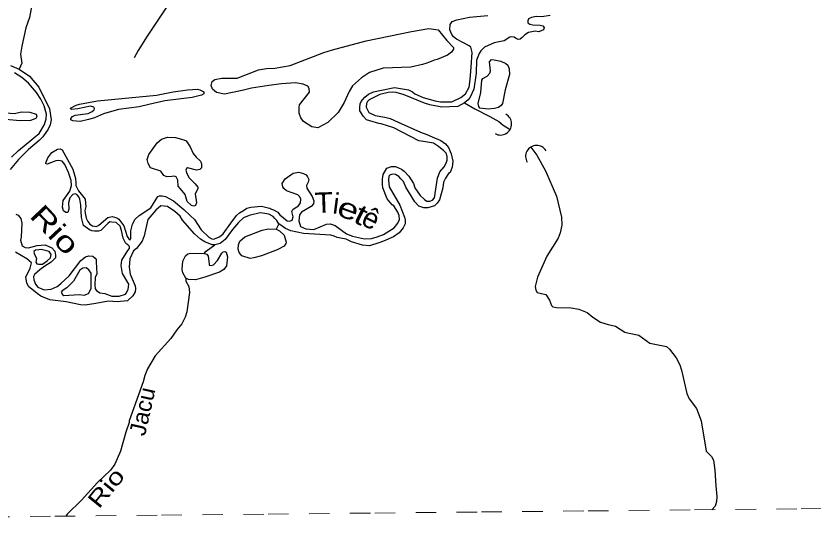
# Model space of a CAD drawing. Extents: x 346.5 to 372.4, y 7400.3 to 7428.2.
# Drawn here: x 350.815 to 354.71, y 7400.32 to 7402.808 of the extents above; entities that cross this region are included whole.
import ezdxf
from ezdxf.enums import TextEntityAlignment as Align

# ---------------------------------------------------------------- set-up
doc = ezdxf.new("R2010")
doc.units = 0
doc.header["$LTSCALE"] = 0.032
doc.linetypes.add('SHORT_DASHED', pattern=[2.7, 1.5, -1.2])
for name, color, linetype, lineweight in [('1', 7, 'Continuous', 25), ('11', 7, 'Continuous', 25), ('2', 7, 'Continuous', 25), ('53', 7, 'SHORT_DASHED', 13), ('7', 7, 'Continuous', 25)]:
    doc.layers.add(name, color=color, linetype=linetype, lineweight=lineweight)
doc.layers.add('61', color=7, linetype='Continuous')

msp = doc.modelspace()

# ---------------------------------------------------------------- linework, layer by layer
at = {"layer": '1'}
msp.add_lwpolyline([(352.0375, 7403.6183), (351.8749, 7403.388), (351.6956, 7403.1266), (351.6877, 7403.1138), (351.6908, 7403.0716), (351.6853, 7403.0612), (351.545, 7402.8413), (351.4565, 7402.709), (351.4119, 7402.6388), (351.3936, 7402.603)], dxfattribs=at)
at = {"layer": '11'}
for centre, start, end in [((353.1832, 7402.2798), 240.5966, 61.2995), ((353.3596, 7402.1208), 30.8412, 211.5442)]:
    msp.add_arc(centre, 0.0541, start, end, dxfattribs=at)
at = {"layer": '2'}
for points in [[(352.4969, 7402.3778), (352.5027, 7402.3902), (352.509, 7402.3985), (352.5203, 7402.4105), (352.5388, 7402.4249), (352.5631, 7402.437), (352.6013, 7402.4457), (352.6645, 7402.4574), (352.7337, 7402.4458), (352.7524, 7402.4372), (352.7642, 7402.4274), (352.8057, 7402.4094), (352.8638, 7402.3921), (352.8899, 7402.3872), (352.9449, 7402.3881), (352.9899, 7402.4084), (353.0116, 7402.4275), (353.0305, 7402.4602), (353.034, 7402.4963), (353.0398, 7402.5575), (353.0451, 7402.6289), (353.0384, 7402.6547), (353.0296, 7402.6618), (352.9683, 7402.6935), (352.9535, 7402.7052), (352.9449, 7402.7174), (352.9361, 7402.7391), (352.9364, 7402.7658), (352.9473, 7402.7801), (352.9702, 7402.7885), (353.0322, 7402.8013), (353.1214, 7402.8102)], [(353.4253, 7402.8091), (353.3842, 7402.8037), (353.3568, 7402.8049), (353.3347, 7402.8006), (353.3197, 7402.7932), (353.3158, 7402.784), (353.3169, 7402.7734), (353.3258, 7402.7679), (353.3418, 7402.7636), (353.3761, 7402.7624), (353.3899, 7402.7589), (353.3963, 7402.751), (353.3928, 7402.7402), (353.3709, 7402.7308), (353.3521, 7402.7325), (353.3202, 7402.7266), (353.3017, 7402.7152), (353.2886, 7402.702), (353.2796, 7402.6946), (353.2691, 7402.6931), (353.2559, 7402.6983), (353.2496, 7402.7041), (353.237, 7402.7062), (353.2284, 7402.7041), (353.2009, 7402.6862), (353.1519, 7402.6759), (353.1048, 7402.6551), (353.0877, 7402.6373), (353.0784, 7402.6249), (353.0658, 7402.5909), (353.0636, 7402.5276), (353.052, 7402.4502), (353.0353, 7402.4101), (353.0249, 7402.397), (353.0074, 7402.3835), (352.974, 7402.3659), (352.8966, 7402.3615), (352.8378, 7402.3732), (352.8124, 7402.3815), (352.7124, 7402.4217), (352.6724, 7402.4334), (352.6535, 7402.435), (352.6335, 7402.4337), (352.5929, 7402.4244), (352.542, 7402.3984), (352.5328, 7402.3897), (352.5278, 7402.3794), (352.5268, 7402.362), (352.5398, 7402.3354), (352.5705, 7402.3206), (352.6179, 7402.3131), (352.6446, 7402.3065), (352.6823, 7402.2879), (352.7919, 7402.2402), (352.8226, 7402.2283), (352.8499, 7402.2162), (352.8914, 7402.1983), (352.9145, 7402.1835), (352.9284, 7402.1645), (352.9412, 7402.1339), (352.9494, 7402.0977), (352.9472, 7402.068), (352.9377, 7402.0434), (352.9295, 7402.0371), (352.9145, 7402.0157), (352.9042, 7401.9951), (352.9005, 7401.9681), (352.8848, 7401.9091), (352.8742, 7401.8926), (352.8605, 7401.8793), (352.828, 7401.8698)], [(350.7883, 7402.5657), (350.8318, 7402.5473), (350.8816, 7402.5133), (350.9265, 7402.4595), (350.9796, 7402.3545), (350.9873, 7402.3008), (350.9828, 7402.2762), (350.9732, 7402.2545), (350.9468, 7402.2169), (350.9295, 7402.1986), (350.8763, 7402.1548), (350.8278, 7402.107), (350.7879, 7402.0566)], [(350.794, 7402.1169), (350.8276, 7402.1506), (350.8923, 7402.2035), (350.9044, 7402.2137), (350.9281, 7402.2328), (350.9544, 7402.2766), (350.9634, 7402.3047), (350.9642, 7402.3277), (350.9539, 7402.3686), (350.9377, 7402.4012), (350.9163, 7402.4337), (350.8771, 7402.4789), (350.8434, 7402.5074), (350.8076, 7402.5293)], [(351.9634, 7401.873), (352.0152, 7401.8777), (352.0539, 7401.869), (352.0637, 7401.8642), (352.0743, 7401.86), (352.0944, 7401.8488), (352.0986, 7401.8434), (352.1055, 7401.8366), (352.1413, 7401.807), (352.1539, 7401.8044), (352.1648, 7401.8098), (352.1701, 7401.826), (352.1659, 7401.8396), (352.1639, 7401.8525), (352.1683, 7401.8621), (352.1792, 7401.8707), (352.1961, 7401.8798), (352.2061, 7401.8948), (352.2077, 7401.9116), (352.2025, 7401.923), (352.1923, 7401.934), (352.1368, 7401.9523), (352.1238, 7401.9645), (352.1197, 7401.973), (352.1154, 7401.9884), (352.1303, 7402.0112), (352.1698, 7402.039), (352.1983, 7402.044), (352.2204, 7402.0383), (352.2333, 7402.0316), (352.2395, 7402.0219), (352.2462, 7402.0091), (352.2432, 7401.9958), (352.2349, 7401.9792), (352.2364, 7401.9669), (352.2632, 7401.9247), (352.2712, 7401.9035), (352.2691, 7401.8902), (352.2581, 7401.8766), (352.2106, 7401.8486), (352.2011, 7401.8365), (352.1983, 7401.8065), (352.2061, 7401.7796), (352.2316, 7401.7669), (352.2705, 7401.7645), (352.3331, 7401.7895), (352.3507, 7401.7914), (352.3744, 7401.7831), (352.4308, 7401.7428), (352.4597, 7401.7311), (352.5188, 7401.7191), (352.5529, 7401.7208), (352.5811, 7401.7284), (352.6121, 7401.7394), (352.6639, 7401.7721), (352.6817, 7401.7951), (352.6897, 7401.8129), (352.6881, 7401.8325), (352.6818, 7401.8488), (352.6623, 7401.8793), (352.6544, 7401.8842), (352.6297, 7401.9138), (352.6079, 7401.9677), (352.6064, 7401.9835), (352.6061, 7402.0099), (352.6097, 7402.033), (352.6281, 7402.0637), (352.6506, 7402.0721), (352.6698, 7402.0712), (352.6991, 7402.0588), (352.712, 7402.0494), (352.735, 7402.0255), (352.7572, 7401.9892), (352.7646, 7401.968), (352.7901, 7401.9299), (352.8116, 7401.9103), (352.8226, 7401.9031), (352.8373, 7401.9021), (352.85, 7401.9068), (352.8605, 7401.9182), (352.8747, 7402.0158), (352.8868, 7402.0459), (352.908, 7402.0708), (352.9151, 7402.0846), (352.9217, 7402.1023), (352.9226, 7402.1215), (352.9183, 7402.1364), (352.9059, 7402.1491), (352.8805, 7402.1705), (352.8562, 7402.1854), (352.8063, 7402.1934), (352.7847, 7402.1974), (352.6615, 7402.2607), (352.6003, 7402.2807), (352.5882, 7402.2815), (352.5442, 7402.2948), (352.529, 7402.3005), (352.5128, 7402.3168), (352.4956, 7402.3436), (352.4964, 7402.36), (352.4969, 7402.3778)], [(351.3288, 7401.5886), (351.333, 7401.6147), (351.3624, 7401.661), (351.3698, 7401.6714), (351.3698, 7401.6818), (351.3624, 7401.6885), (351.3527, 7401.6951), (351.3392, 7401.7213), (351.3312, 7401.7589), (351.3238, 7401.7797), (351.3054, 7401.7977), (351.2846, 7401.8008), (351.2742, 7401.8012), (351.2638, 7401.7931), (351.2305, 7401.7592), (351.2188, 7401.7554), (351.1999, 7401.7566), (351.1856, 7401.758), (351.1741, 7401.7631), (351.1457, 7401.7845), (351.1349, 7401.8221), (351.1322, 7401.8836), (351.1268, 7401.9127), (351.1227, 7401.9237), (351.1129, 7401.9354), (351.1048, 7401.9382), (351.0927, 7401.9359), (351.0784, 7401.9183), (351.0727, 7401.8941), (351.0733, 7401.8635), (351.0696, 7401.8478), (351.0595, 7401.8472), (351.0483, 7401.855), (351.0422, 7401.8741), (351.0458, 7401.9055), (351.0787, 7401.9509), (351.0863, 7401.9791), (351.0849, 7402.0028), (351.0717, 7402.0424), (351.0538, 7402.0822), (351.0404, 7402.0975), (351.0249, 7402.1012), (351.0097, 7402.0998), (350.9681, 7402.0842), (350.9621, 7402.0852), (350.9616, 7402.0895), (350.9713, 7402.1148), (350.9903, 7402.1408), (351.0185, 7402.1574), (351.0322, 7402.1584), (351.0406, 7402.1536), (351.0933, 7402.0583), (351.1057, 7402.014), (351.1074, 7401.9943), (351.1079, 7401.9792), (351.1206, 7401.9537), (351.1531, 7401.9123), (351.1556, 7401.8912), (351.1565, 7401.8758), (351.1526, 7401.8563), (351.1541, 7401.8445), (351.1578, 7401.82), (351.1659, 7401.8035), (351.1763, 7401.7901), (351.1889, 7401.7814), (351.2082, 7401.7792), (351.2208, 7401.7859), (351.2639, 7401.8225), (351.285, 7401.8269), (351.3082, 7401.8214), (351.3175, 7401.8144), (351.3427, 7401.7823), (351.3591, 7401.7301), (351.3664, 7401.718), (351.3731, 7401.7141), (351.3775, 7401.7208), (351.3764, 7401.7583), (351.3841, 7401.7897), (351.3986, 7401.8141), (351.418, 7401.8331), (351.4742, 7401.8696), (351.5092, 7401.9253), (351.5162, 7401.9291), (351.5296, 7401.9294), (351.5469, 7401.9255), (351.5846, 7401.9037), (351.6358, 7401.8626), (351.6674, 7401.8325), (351.6871, 7401.8128), (351.7208, 7401.7625), (351.7583, 7401.7266), (351.7731, 7401.718), (351.781, 7401.7168), (351.8098, 7401.7276), (351.8279, 7401.7429), (351.8646, 7401.7945), (351.8925, 7401.8323), (351.9083, 7401.8458), (351.9265, 7401.8567), (351.9429, 7401.8686), (351.9634, 7401.873)], [(352.828, 7401.8698), (352.8088, 7401.8707), (352.7844, 7401.8774), (352.7648, 7401.9001), (352.72, 7401.9707), (352.7095, 7401.998), (352.6962, 7402.0124), (352.6856, 7402.0237), (352.6698, 7402.0321), (352.6544, 7402.0347), (352.643, 7402.0301), (352.6372, 7402.024), (352.635, 7402.0069), (352.6394, 7401.9727), (352.6905, 7401.8834), (352.7138, 7401.8243), (352.7174, 7401.8102), (352.7167, 7401.792), (352.7081, 7401.7723), (352.6872, 7401.7472), (352.6594, 7401.7291), (352.6105, 7401.7066), (352.5885, 7401.6994), (352.5437, 7401.6848), (352.5087, 7401.6876), (352.4552, 7401.7045), (352.4295, 7401.7165), (352.3852, 7401.7254), (352.371, 7401.7308), (352.3543, 7401.7367), (352.2201, 7401.7453), (352.159, 7401.7569), (352.1329, 7401.7684), (352.0992, 7401.7912), (352.0896, 7401.8088), (352.0804, 7401.8176), (352.0719, 7401.8278), (352.0504, 7401.8397), (352.0311, 7401.843), (352.0094, 7401.846), (351.9552, 7401.8327), (351.9269, 7401.8207), (351.9021, 7401.7986), (351.8728, 7401.7643), (351.8383, 7401.7145), (351.813, 7401.6958), (351.7876, 7401.6889), (351.7738, 7401.6896), (351.7379, 7401.704), (351.7173, 7401.7166), (351.688, 7401.7437), (351.6292, 7401.8101), (351.6184, 7401.8286), (351.5923, 7401.8513), (351.5551, 7401.8764), (351.5238, 7401.8791), (351.4993, 7401.8586), (351.4595, 7401.8125), (351.4413, 7401.7324), (351.4323, 7401.7074), (351.4038, 7401.6712), (351.3904, 7401.66), (351.3722, 7401.6207), (351.3684, 7401.5803), (351.3738, 7401.5456), (351.3979, 7401.489), (351.3999, 7401.4747), (351.398, 7401.4594), (351.3862, 7401.4395), (351.3609, 7401.4161), (351.3097, 7401.4107), (351.2684, 7401.4135), (351.2049, 7401.4024), (351.1532, 7401.3951), (351.1307, 7401.3968), (351.0603, 7401.4106), (350.9812, 7401.4212), (350.9369, 7401.4384), (350.9186, 7401.4514), (350.8772, 7401.4864), (350.8684, 7401.504), (350.8644, 7401.5311), (350.8842, 7401.5745), (350.8911, 7401.6005), (350.8681, 7401.621), (350.8135, 7401.6539)], [(350.8153, 7401.8392), (350.8264, 7401.8342), (350.8396, 7401.8173), (350.8446, 7401.7959), (350.8405, 7401.7264), (350.8373, 7401.7115), (350.8461, 7401.6843), (350.8597, 7401.677), (350.877, 7401.675), (350.9189, 7401.686), (350.9585, 7401.6893), (350.9907, 7401.6748), (351.0055, 7401.659), (351.0086, 7401.6383), (351.008, 7401.6264), (350.9986, 7401.6165), (350.9872, 7401.6042), (350.9569, 7401.5854), (350.9317, 7401.5678), (350.9055, 7401.5439), (350.9009, 7401.5348), (350.9021, 7401.5175), (350.9101, 7401.4966), (350.9229, 7401.4828), (350.953, 7401.4695), (350.9872, 7401.4721), (351.0162, 7401.4857), (351.0236, 7401.4899), (351.0356, 7401.5014), (351.076, 7401.5385), (351.133, 7401.6126), (351.1557, 7401.631), (351.1707, 7401.6348), (351.191, 7401.6333), (351.2021, 7401.6236), (351.2073, 7401.6169), (351.2079, 7401.6058), (351.2102, 7401.548), (351.2025, 7401.53), (351.2012, 7401.4942), (351.2028, 7401.4735), (351.2084, 7401.4655), (351.2253, 7401.4542), (351.2489, 7401.4518), (351.2831, 7401.4381), (351.3201, 7401.4384), (351.3508, 7401.4488), (351.3545, 7401.4528), (351.3641, 7401.4709), (351.3669, 7401.4978), (351.3353, 7401.5487), (351.3288, 7401.5886)]]:
    msp.add_lwpolyline(points, dxfattribs=at)
for points in [[(351.9212, 7402.4436), (351.8344, 7402.4256), (351.7952, 7402.4337), (351.7757, 7402.4491), (351.7694, 7402.4678), (351.7736, 7402.4876), (351.7865, 7402.4972), (351.8211, 7402.5043), (351.8958, 7402.5035), (352.0009, 7402.5444), (352.0395, 7402.5512), (352.08, 7402.5519), (352.1558, 7402.5655), (352.319, 7402.6288), (352.3619, 7402.6425), (352.5263, 7402.6859), (352.7487, 7402.7322), (352.8324, 7402.7456), (352.8791, 7402.7401), (352.9205, 7402.6875), (352.9527, 7402.6528), (352.9529, 7402.6447), (352.9442, 7402.6301), (352.9237, 7402.6165), (352.8743, 7402.5942), (352.8592, 7402.591), (352.8524, 7402.5879), (352.8315, 7402.5798), (352.8226, 7402.5768), (352.8021, 7402.57), (352.7448, 7402.5576), (352.6101, 7402.5528), (352.5426, 7402.5313), (352.5042, 7402.505), (352.4595, 7402.4669), (352.443, 7402.4383), (352.4199, 7402.384), (352.3904, 7402.3354), (352.3394, 7402.2867), (352.2902, 7402.2617), (352.2612, 7402.2652), (352.2199, 7402.2913), (352.2077, 7402.3097), (352.1999, 7402.3319), (352.1985, 7402.361), (352.2014, 7402.3735), (352.2496, 7402.4348), (352.2473, 7402.4533), (352.2419, 7402.464), (352.2188, 7402.4739), (352.1821, 7402.4802), (352.1124, 7402.4758), (352.0503, 7402.4675), (351.9658, 7402.4547)], [(353.1925, 7402.3803), (353.1863, 7402.3697), (353.1733, 7402.3609), (353.1533, 7402.3557), (353.1224, 7402.3519), (353.0828, 7402.3572), (353.0765, 7402.3648), (353.0743, 7402.38), (353.087, 7402.4334), (353.0925, 7402.4944), (353.0973, 7402.5013), (353.1175, 7402.514), (353.1305, 7402.5275), (353.1343, 7402.5401), (353.1296, 7402.584), (353.139, 7402.5946), (353.1514, 7402.5938), (353.1847, 7402.5867), (353.2084, 7402.575), (353.2185, 7402.5664), (353.2258, 7402.5498), (353.2267, 7402.5214), (353.2052, 7402.4474)], [(351.1699, 7402.3015), (351.1293, 7402.2923), (351.1094, 7402.2931), (351.0926, 7402.295), (351.0841, 7402.3002), (351.0834, 7402.3068), (351.092, 7402.3166), (351.104, 7402.3236), (351.1685, 7402.3309), (351.1884, 7402.34), (351.1977, 7402.3492), (351.1987, 7402.3562), (351.1953, 7402.3622), (351.1799, 7402.3668), (351.1183, 7402.3532), (351.087, 7402.3502), (351.0824, 7402.355), (351.0821, 7402.3572), (351.1094, 7402.3718), (351.1257, 7402.3767), (351.2132, 7402.3931), (351.5029, 7402.4201), (351.5843, 7402.4369), (351.653, 7402.4462), (351.7019, 7402.4491), (351.7143, 7402.4471), (351.7337, 7402.4376), (351.7326, 7402.4278), (351.7223, 7402.4203), (351.6767, 7402.4097), (351.5436, 7402.3926), (351.4653, 7402.3742), (351.4167, 7402.3631), (351.3166, 7402.3512), (351.2438, 7402.3293), (351.1986, 7402.3092)], [(350.836, 7402.2959), (350.7272, 7402.3049), (350.5448, 7402.3269), (350.433, 7402.3239), (350.4138, 7402.3293), (350.3993, 7402.3391), (350.396, 7402.3451), (350.398, 7402.3509), (350.4057, 7402.3565), (350.4585, 7402.3809), (350.4699, 7402.3829), (350.5125, 7402.3774), (350.6094, 7402.3554), (350.7254, 7402.3368), (350.807, 7402.3314), (350.8442, 7402.3388), (350.8839, 7402.3382), (350.9137, 7402.3271), (350.9169, 7402.3162), (350.913, 7402.3067), (350.8869, 7402.2964)], [(351.4616, 7402.0859), (351.4571, 7402.1062), (351.4652, 7402.1302), (351.5055, 7402.1872), (351.5271, 7402.2059), (351.5565, 7402.2151), (351.5953, 7402.2133), (351.6354, 7402.2031), (351.6472, 7402.1969), (351.6674, 7402.1678), (351.6813, 7402.136), (351.696, 7402.1175), (351.7177, 7402.0975), (351.7228, 7402.0844), (351.7223, 7402.0657), (351.7139, 7402.0572), (351.6983, 7402.0534), (351.6531, 7402.0652), (351.6491, 7402.0629), (351.6462, 7402.0544), (351.6487, 7402.0422), (351.6605, 7402.0181), (351.6918, 7401.9881), (351.7048, 7401.9714), (351.7036, 7401.9636), (351.6905, 7401.9389), (351.6977, 7401.8944), (351.6929, 7401.8811), (351.6853, 7401.8779), (351.6728, 7401.8819), (351.6522, 7401.9004), (351.6414, 7401.9355), (351.6186, 7401.963), (351.6085, 7401.9767), (351.6071, 7402.0055), (351.5987, 7402.0216), (351.5884, 7402.0252), (351.5769, 7402.0227), (351.5531, 7402.0213), (351.5382, 7402.0283), (351.5237, 7402.0484), (351.4734, 7402.0654)], [(352.0872, 7401.7658), (352.1025, 7401.758), (352.1258, 7401.736), (352.1365, 7401.7025), (352.1346, 7401.695), (352.1253, 7401.6834), (352.0917, 7401.6649), (352.0146, 7401.6359), (351.9783, 7401.625), (351.9591, 7401.6228), (351.9194, 7401.6348), (351.9055, 7401.6513), (351.9008, 7401.6675), (351.9025, 7401.6887), (351.9095, 7401.7079), (351.9332, 7401.7278), (352.0185, 7401.7609), (352.0494, 7401.7671)], [(350.9273, 7401.6649), (350.9116, 7401.6633), (350.9035, 7401.6574), (350.9051, 7401.6461), (350.9151, 7401.6231), (350.9118, 7401.6044), (350.9176, 7401.5967), (350.9254, 7401.5943), (350.9443, 7401.595), (350.9687, 7401.6106), (350.9843, 7401.6255), (350.988, 7401.6425), (350.9771, 7401.6563), (350.9379, 7401.6658)], [(351.6452, 7401.5261), (351.6303, 7401.5517), (351.6269, 7401.5684), (351.631, 7401.6095), (351.6439, 7401.6347), (351.6554, 7401.6445), (351.6681, 7401.649), (351.7348, 7401.6463), (351.7479, 7401.6429), (351.7538, 7401.634), (351.7592, 7401.5969), (351.7598, 7401.5902), (351.7699, 7401.588), (351.7809, 7401.5916), (351.8003, 7401.6119), (351.8214, 7401.6492), (351.8285, 7401.6557), (351.8366, 7401.6565), (351.8418, 7401.653), (351.8496, 7401.6303), (351.8442, 7401.5873), (351.8316, 7401.5682), (351.8093, 7401.5553), (351.7387, 7401.5319), (351.6932, 7401.5183), (351.6582, 7401.5199)], [(351.1247, 7401.4459), (351.1489, 7401.4439), (351.1696, 7401.4508), (351.183, 7401.4755), (351.1827, 7401.5501), (351.1709, 7401.5668), (351.159, 7401.5775), (351.1418, 7401.5746), (351.1272, 7401.5656), (351.0968, 7401.5113), (351.0646, 7401.4795), (351.0405, 7401.4637), (351.0365, 7401.4578), (351.0423, 7401.446), (351.0494, 7401.4418)]]:
    msp.add_lwpolyline(points, close=True, dxfattribs=at)
at = {"layer": '53'}
msp.add_lwpolyline([(346.8371, 7400.32), (347.3582, 7400.3254), (347.8792, 7400.3309), (348.4002, 7400.3363), (348.9213, 7400.3416), (349.4423, 7400.347), (349.9634, 7400.3523), (350.4844, 7400.3576), (351.0054, 7400.3629), (351.5265, 7400.3682), (352.0475, 7400.3735), (352.5685, 7400.3787), (353.0896, 7400.384), (353.6106, 7400.3892), (354.1316, 7400.3944), (354.6527, 7400.3995), (355.1737, 7400.4047), (355.6947, 7400.4098), (356.2158, 7400.4149), (356.7368, 7400.42), (357.2578, 7400.4251), (357.7789, 7400.4302), (358.2999, 7400.4352), (358.8209, 7400.4403)], dxfattribs=at)
at = {"layer": '7'}
msp.add_line((352.0992, 7401.7912), (352.0872, 7401.7658), dxfattribs=at)
for points in [[(350.9006, 7402.9073), (350.8812, 7402.7998), (350.8644, 7402.7488), (350.8437, 7402.6596), (350.8373, 7402.6213), (350.8437, 7402.5767), (350.8318, 7402.5473)], [(353.0074, 7402.3835), (353.0571, 7402.354), (353.1309, 7402.3169), (353.1748, 7402.2914), (353.1963, 7402.2746), (353.2305, 7402.2535)], [(353.3316, 7402.1671), (353.3604, 7402.1272), (353.4027, 7402.0507), (353.4569, 7401.9264), (353.4816, 7401.8244), (353.4824, 7401.7861), (353.4744, 7401.7479), (353.464, 7401.7224), (353.4091, 7401.6331), (353.3636, 7401.5311), (353.3517, 7401.4857), (353.3549, 7401.4673), (353.3621, 7401.457), (353.4051, 7401.4458), (353.4218, 7401.4195), (353.4322, 7401.3924), (353.4386, 7401.3868), (353.4561, 7401.3836), (353.5278, 7401.382), (353.5661, 7401.3757), (353.6059, 7401.3581), (353.6338, 7401.3358), (353.6713, 7401.3111), (353.7095, 7401.2992), (353.7446, 7401.2912), (353.7908, 7401.2633), (353.8036, 7401.2585), (353.8586, 7401.2482), (353.9127, 7401.2083), (353.994, 7401.1924), (354.0084, 7401.1788), (354.041, 7401.1374), (354.0594, 7401.1023), (354.0673, 7401.0768), (354.0936, 7400.9621), (354.1056, 7400.9366), (354.1415, 7400.8895), (354.1638, 7400.8298), (354.1877, 7400.6815), (354.214, 7400.6544), (354.2243, 7400.6377), (354.2307, 7400.5875), (354.2347, 7400.511), (354.2395, 7400.46), (354.2379, 7400.4345), (354.2315, 7400.413), (354.215, 7400.3952)], [(351.7348, 7401.6463), (351.745, 7401.6576), (351.7876, 7401.6889)], [(351.6452, 7401.5261), (351.646, 7401.5121), (351.6598, 7401.4849), (351.6638, 7401.4562), (351.6502, 7401.3621), (351.6422, 7401.3358), (351.6255, 7401.3032), (351.6016, 7401.2745), (351.5721, 7401.2314), (351.4964, 7401.1462), (351.4581, 7401.0832), (351.4446, 7401.0513), (351.4366, 7401.0194), (351.3691, 7400.8287), (351.3691, 7400.8204), (351.3521, 7400.7732), (351.3266, 7400.6815), (351.2987, 7400.6178), (351.2772, 7400.5875), (351.2135, 7400.5285), (351.1354, 7400.4409), (351.0656, 7400.3728), (351.059, 7400.3634)]]:
    msp.add_lwpolyline(points, dxfattribs=at)

# ---------------------------------------------------------------- texts
at = {"layer": '61'}
for s, height, rotation, width, p in [('T', 0.1, 2.045, 1.1, (352.3214, 7401.8458)), ('e', 0.1, 339.988, 1.35, (352.4237, 7401.8186)), ('Rio', 0.1, 313.349, 1.35, (350.9695, 7401.7289)), ('t', 0.1, 333.435, 1.35, (352.4797, 7401.7923)), ('Jacu', 0.08, 77.386, 1.05, (351.4717, 7400.8669)), ('Rio', 0.08, 50.842, 1.3, (351.2867, 7400.4766))]:
    msp.add_text(s, height=height, rotation=rotation, dxfattribs=dict(at, width=width)).set_placement(p, align=Align.CENTER)
for s, rotation, p in [('i', 352.48, (352.374, 7401.8418)), ('ê', 333.435, (352.529, 7401.7741))]:
    msp.add_text(s, height=0.1, rotation=rotation, dxfattribs=at).set_placement(p, align=Align.CENTER)

doc.saveas('drawing.dxf')
